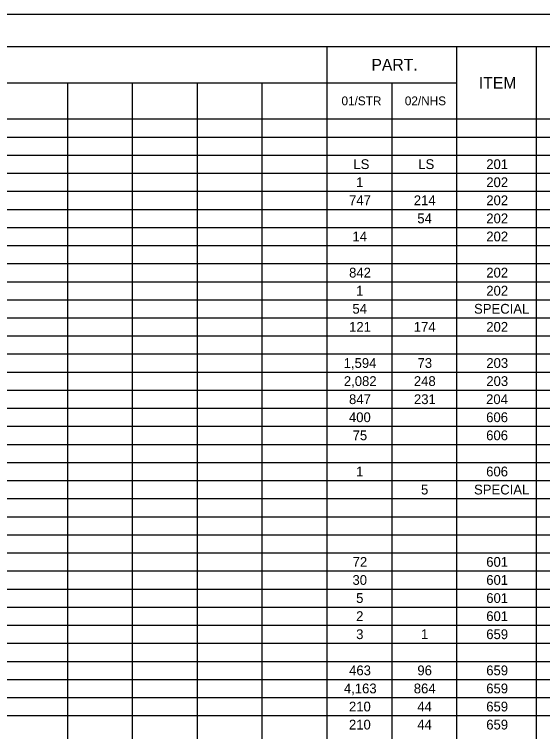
# Model space of a CAD drawing. Extents: x 0 to 1700, y 0 to 1100.
# Drawn here: x 436 to 845, y 545 to 1100 of the extents above; entities that cross this region are included whole.
import ezdxf

# ---------------------------------------------------------------- set-up
doc = ezdxf.new("R2010")
doc.units = 0
for name, color, linetype in [('SH_Border', 7, 'Continuous'), ('SH_Cut_Line', 7, 'Continuous'), ('SH_Text', 7, 'Continuous')]:
    doc.layers.add(name, color=color, linetype=linetype)

msp = doc.modelspace()

# ---------------------------------------------------------------- linework, layer by layer
at = {"layer": 'SH_Border'}
msp.add_lwpolyline([(75, 1075), (1675, 1075), (1675, 25), (75, 25)], close=True, dxfattribs=at)
at = {"layer": 'SH_Cut_Line'}
msp.add_lwpolyline([(0, 0), (1700, 0), (1700, 1100), (0, 1100)], close=True, dxfattribs=at)
at = {"layer": 'SH_Text'}
for p, q in [((75, 1075), (1600, 1075)), ((677.75, 1075), (677.75, 25.12)), ((778.21, 1075), (778.21, 25.12)), ((839.97, 1075), (839.97, 25.12)), ((75, 1047), (778.21, 1047)), ((476.84, 1047), (476.84, 25.12)), ((527.07, 1047), (527.07, 25.12)), ((577.29, 1047), (577.29, 25.12)), ((627.52, 1047), (627.52, 25.12)), ((727.98, 1047), (727.98, 25.12)), ((75, 1019.01), (1600, 1019.01)), ((75, 1005.01), (1600, 1005.01)), ((75, 991.01), (1600, 991.01)), ((75, 977.01), (1600, 977.01)), ((75, 963.01), (1600, 963.01)), ((75, 949.01), (1600, 949.01)), ((75, 935.02), (1600, 935.02)), ((75, 921.02), (1600, 921.02)), ((75, 907.02), (1600, 907.02)), ((75, 893.02), (1600, 893.02)), ((75, 879.02), (1600, 879.02)), ((75, 865.02), (1600, 865.02)), ((75, 851.03), (1600, 851.03)), ((75, 837.03), (1600, 837.03)), ((75, 823.03), (1600, 823.03)), ((75, 809.03), (1600, 809.03)), ((75, 795.03), (1600, 795.03)), ((75, 781.03), (1600, 781.03)), ((75, 767.04), (1600, 767.04)), ((75, 753.04), (1600, 753.04)), ((75, 739.04), (1600, 739.04)), ((75, 725.04), (1600, 725.04)), ((75, 711.04), (1600, 711.04)), ((75, 697.04), (1600, 697.04)), ((75, 683.05), (1600, 683.05)), ((75, 669.05), (1600, 669.05)), ((75, 655.05), (1600, 655.05)), ((75, 641.05), (1600, 641.05)), ((75, 627.05), (1600, 627.05)), ((75, 613.05), (1600, 613.05)), ((75, 599.06), (1600, 599.06)), ((75, 585.06), (1600, 585.06)), ((75, 571.06), (1600, 571.06)), ((75, 557.06), (1600, 557.06))]:
    msp.add_line(p, q, dxfattribs=at)

# ---------------------------------------------------------------- texts
for s, height, p in [('PART.', 9.091, (712.31, 1056.46)), ('ITEM', 9.091, (795.51, 1042.46)), ('01/STR', 6.818, (689.12, 1029.6)), ('02/NHS', 6.818, (738.16, 1029.6)), ('LS', 7.576, (698.34, 980.22)), ('LS', 7.576, (748.57, 980.22)), ('201', 7.576, (801.22, 980.22)), ('1', 7.58, (700.44, 966.22)), ('202', 7.576, (801.23, 966.22)), ('747', 7.576, (694.95, 952.23)), ('214', 7.576, (745.09, 952.23)), ('202', 7.576, (801.23, 952.23)), ('54', 7.576, (747.81, 938.23)), ('202', 7.576, (801.23, 938.23)), ('14', 7.576, (697.58, 924.23)), ('202', 7.576, (801.23, 924.23)), ('842', 7.576, (695, 896.23)), ('202', 7.576, (801.23, 896.23)), ('1', 7.58, (700.44, 882.23)), ('202', 7.576, (801.23, 882.23)), ('54', 7.576, (697.58, 868.24)), ('SPECIAL', 7.576, (791.75, 868.24)), ('121', 7.576, (695, 854.24)), ('174', 7.576, (745.09, 854.24)), ('202', 7.576, (801.23, 854.24)), ('1,594', 7.576, (690.8, 826.24)), ('73', 7.576, (747.98, 826.24)), ('203', 7.576, (801.26, 826.24)), ('2,082', 7.576, (690.94, 812.24)), ('248', 7.576, (745.16, 812.24)), ('203', 7.576, (801.26, 812.24)), ('847', 7.576, (694.95, 798.24)), ('231', 7.576, (745.23, 798.24)), ('204', 7.576, (801.08, 798.24)), ('400', 7.576, (694.89, 784.25)), ('606', 7.576, (801.14, 784.25)), ('75', 7.576, (697.74, 770.25)), ('606', 7.576, (801.14, 770.25)), ('1', 7.58, (700.44, 742.25)), ('606', 7.576, (801.14, 742.25)), ('5', 7.58, (750.69, 728.25)), ('SPECIAL', 7.576, (791.75, 728.25)), ('72', 7.576, (697.72, 672.26)), ('601', 7.576, (801.22, 672.26)), ('30', 7.576, (697.61, 658.26)), ('601', 7.576, (801.22, 658.26)), ('5', 7.58, (700.46, 644.26)), ('601', 7.576, (801.22, 644.26)), ('2', 7.58, (700.45, 630.26)), ('601', 7.576, (801.22, 630.26)), ('3', 7.58, (700.47, 616.26)), ('1', 7.58, (750.67, 616.26)), ('659', 7.576, (801.2, 616.26)), ('463', 7.576, (695.03, 588.27)), ('96', 7.576, (747.87, 588.27)), ('659', 7.576, (801.2, 588.27)), ('4,163', 7.576, (690.97, 574.27)), ('864', 7.576, (745.09, 574.27)), ('659', 7.576, (801.2, 574.27)), ('210', 7.576, (694.89, 560.27)), ('44', 7.576, (747.81, 560.27)), ('659', 7.576, (801.2, 560.27)), ('210', 7.576, (694.89, 546.27)), ('44', 7.576, (747.81, 546.27)), ('659', 7.576, (801.2, 546.27))]:
    msp.add_text(s, height=height, dxfattribs=at).set_placement(p)

doc.saveas('drawing.dxf')
